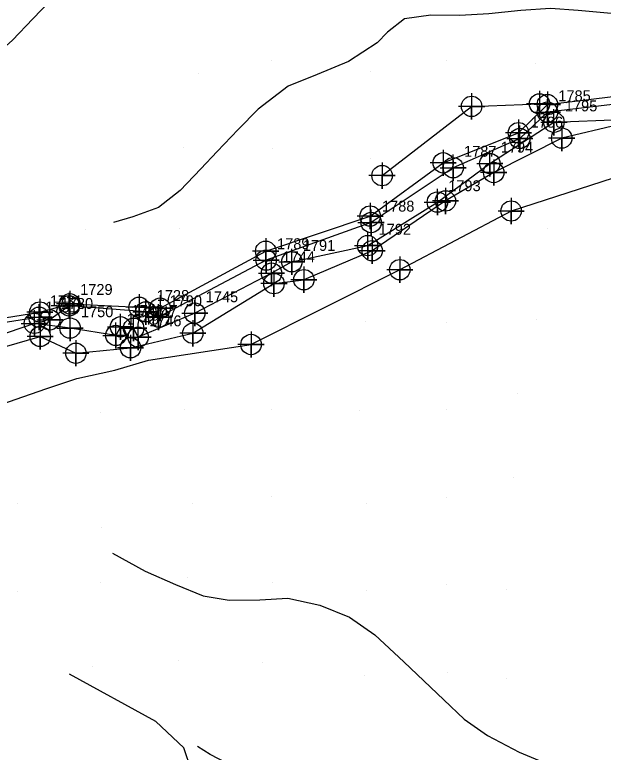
# Model space of a CAD drawing. Extents: x 1497074 to 1501343, y 481943 to 486114.
# Drawn here: x 1498608.9 to 1498743.8, y 484626.5 to 484795.7 of the extents above; entities that cross this region are included whole.
import ezdxf

# ---------------------------------------------------------------- set-up
doc = ezdxf.new("R2010")
doc.units = 0
for name, color, linetype in [('Exist DTM Breakline', 7, 'Continuous'), ('Exist DTM Breakline Cogo Point CELL', 7, 'Continuous'), ('Exist Hydro Stream or Body of Water', 7, 'Continuous'), ('Exist Hydro Stream or Body of Water Cogo Number', 7, 'Continuous'), ('Exist Hydro Stream or Body of Water Cogo Point CELL', 7, 'Continuous'), ('PH Exist DTM Breakline', 7, 'Continuous'), ('PH Exist DTM Point', 7, 'Continuous')]:
    doc.layers.add(name, color=color, linetype=linetype)

msp = doc.modelspace()

# ---------------------------------------------------------------- linework, layer by layer
at = {"layer": 'Exist DTM Breakline'}
for points in [[(1498642.2, 484728.41), (1498666.42, 484741.46), (1498690.37, 484749.54), (1498707.14, 484761.75), (1498724.39, 484768.67), (1498731.03, 484775.11), (1498755.48, 484778.15), (1498768.96, 484780.58), (1498783.61, 484785.4), (1498803.34, 484788.6), (1498815.05, 484790.23)], [(1498818.6, 484781.5), (1498803.72, 484775.91), (1498783.12, 484775.55), (1498771.11, 484773.41), (1498766.97, 484764.98), (1498756.64, 484762.17), (1498749.4, 484764.8), (1498747.24, 484770.45), (1498734.31, 484767.43), (1498718.71, 484759.53), (1498707.65, 484753), (1498690.86, 484741.59), (1498675.18, 484734.94)], [(1498693.11, 484758.81), (1498713.65, 484774.71), (1498729.23, 484775.27)], [(1498751.28, 484759.9), (1498722.71, 484750.7), (1498697.19, 484737.24), (1498663.06, 484720.07)], [(1498592.95, 484715.67), (1498614.71, 484721.92), (1498622.89, 484718.07), (1498635.42, 484719.32), (1498649.7, 484722.64), (1498668.32, 484734.04), (1498675.18, 484734.94)], [(1498561.97, 484712.06), (1498567.31, 484714.79), (1498573.02, 484716.73), (1498578.66, 484717.48), (1498586.51, 484720.09), (1498598.83, 484724.96), (1498614.61, 484727.53), (1498621.47, 484729.41), (1498637.39, 484728.61), (1498642.2, 484728.41)]]:
    msp.add_lwpolyline(points, dxfattribs=at)
at = {"layer": 'Exist DTM Breakline Cogo Point CELL'}
for points in [[(1498713.65, 484777.71), (1498713.65, 484771.71), (1498713.65, 484774.71), (1498716.65, 484774.71), (1498710.65, 484774.71)], [(1498729.23, 484778.27), (1498729.23, 484772.27), (1498729.23, 484775.27), (1498732.23, 484775.27), (1498726.23, 484775.27)], [(1498731.03, 484778.11), (1498731.03, 484772.11), (1498731.03, 484775.11), (1498734.03, 484775.11), (1498728.03, 484775.11)], [(1498724.39, 484771.67), (1498724.39, 484765.67), (1498724.39, 484768.67), (1498727.39, 484768.67), (1498721.39, 484768.67)], [(1498734.31, 484770.43), (1498734.31, 484764.43), (1498734.31, 484767.43), (1498737.31, 484767.43), (1498731.31, 484767.43)], [(1498707.14, 484764.75), (1498707.14, 484758.75), (1498707.14, 484761.75), (1498710.14, 484761.75), (1498704.14, 484761.75)], [(1498718.71, 484762.53), (1498718.71, 484756.53), (1498718.71, 484759.53), (1498721.71, 484759.53), (1498715.71, 484759.53)], [(1498693.11, 484761.81), (1498693.11, 484755.81), (1498693.11, 484758.81), (1498696.11, 484758.81), (1498690.11, 484758.81)], [(1498707.65, 484756), (1498707.65, 484750), (1498707.65, 484753), (1498710.65, 484753), (1498704.65, 484753)], [(1498690.37, 484752.54), (1498690.37, 484746.54), (1498690.37, 484749.54), (1498693.37, 484749.54), (1498687.37, 484749.54)], [(1498722.71, 484753.7), (1498722.71, 484747.7), (1498722.71, 484750.7), (1498725.71, 484750.7), (1498719.71, 484750.7)], [(1498666.42, 484744.46), (1498666.42, 484738.46), (1498666.42, 484741.46), (1498669.42, 484741.46), (1498663.42, 484741.46)], [(1498690.86, 484744.59), (1498690.86, 484738.59), (1498690.86, 484741.59), (1498693.86, 484741.59), (1498687.86, 484741.59)], [(1498697.19, 484740.24), (1498697.19, 484734.24), (1498697.19, 484737.24), (1498700.19, 484737.24), (1498694.19, 484737.24)], [(1498675.18, 484737.94), (1498675.18, 484731.94), (1498675.18, 484734.94), (1498678.18, 484734.94), (1498672.18, 484734.94)], [(1498668.32, 484737.04), (1498668.32, 484731.04), (1498668.32, 484734.04), (1498671.32, 484734.04), (1498665.32, 484734.04)], [(1498621.47, 484732.41), (1498621.47, 484726.41), (1498621.47, 484729.41), (1498624.47, 484729.41), (1498618.47, 484729.41)], [(1498614.61, 484730.53), (1498614.61, 484724.53), (1498614.61, 484727.53), (1498617.61, 484727.53), (1498611.61, 484727.53)], [(1498637.39, 484731.61), (1498637.39, 484725.61), (1498637.39, 484728.61), (1498640.39, 484728.61), (1498634.39, 484728.61)], [(1498642.2, 484731.41), (1498642.2, 484725.41), (1498642.2, 484728.41), (1498645.2, 484728.41), (1498639.2, 484728.41)], [(1498649.7, 484725.64), (1498649.7, 484719.64), (1498649.7, 484722.64), (1498652.7, 484722.64), (1498646.7, 484722.64)], [(1498614.71, 484724.92), (1498614.71, 484718.92), (1498614.71, 484721.92), (1498617.71, 484721.92), (1498611.71, 484721.92)], [(1498635.42, 484722.32), (1498635.42, 484716.32), (1498635.42, 484719.32), (1498638.42, 484719.32), (1498632.42, 484719.32)], [(1498663.06, 484723.07), (1498663.06, 484717.07), (1498663.06, 484720.07), (1498666.06, 484720.07), (1498660.06, 484720.07)], [(1498622.89, 484721.07), (1498622.89, 484715.07), (1498622.89, 484718.07), (1498625.89, 484718.07), (1498619.89, 484718.07)]]:
    msp.add_lwpolyline(points, dxfattribs=at)
for centre in [(1498713.65, 484774.71), (1498729.23, 484775.27), (1498731.03, 484775.11), (1498724.39, 484768.67), (1498734.31, 484767.43), (1498707.14, 484761.75), (1498693.11, 484758.81), (1498718.71, 484759.53), (1498707.65, 484753), (1498722.71, 484750.7), (1498690.37, 484749.54), (1498690.86, 484741.59), (1498666.42, 484741.46), (1498697.19, 484737.24), (1498675.18, 484734.94), (1498668.32, 484734.04), (1498621.47, 484729.41), (1498637.39, 484728.61), (1498642.2, 484728.41), (1498614.61, 484727.53), (1498614.71, 484721.92), (1498649.7, 484722.64), (1498663.06, 484720.07), (1498622.89, 484718.07), (1498635.42, 484719.32)]:
    msp.add_circle(centre, 2.34, dxfattribs=at)
at = {"layer": 'Exist Hydro Stream or Body of Water'}
for points in [[(1498815.48, 484787.21), (1498804.14, 484782.17), (1498784.36, 484782.64), (1498769.3, 484778.29), (1498757.64, 484776.52), (1498731.04, 484773.39), (1498724.7, 484767.33), (1498709.42, 484760.64), (1498690.59, 484748.07), (1498666.52, 484739.44), (1498641.87, 484726.36)], [(1498672.43, 484739.05), (1498689.81, 484742.76), (1498705.79, 484752.75), (1498717.83, 484761.59), (1498732.54, 484771.06), (1498747.88, 484771.66), (1498771.96, 484776.08), (1498782, 484777.24), (1498803.41, 484778.4), (1498816.84, 484784.96)], [(1498672.43, 484739.05), (1498667.77, 484736.45), (1498650.16, 484727.27), (1498637.17, 484721.75), (1498636.13, 484723.81), (1498633.12, 484724.13), (1498632.05, 484722.16), (1498621.54, 484723.84), (1498613.36, 484724.93), (1498592.05, 484717.66)], [(1498641.87, 484726.36), (1498638.93, 484727.56), (1498621.37, 484728.94), (1498616.9, 484725.74), (1498614.44, 484726.33), (1498598.42, 484723.81), (1498587.31, 484717.39), (1498578.44, 484715.65), (1498572.56, 484714.47), (1498568.25, 484712.81), (1498562.8, 484710.02)]]:
    msp.add_lwpolyline(points, dxfattribs=at)
at = {"layer": 'Exist Hydro Stream or Body of Water Cogo Point CELL'}
for points in [[(1498728.04, 484773.39), (1498734.04, 484773.39), (1498731.04, 484773.39), (1498731.04, 484770.39), (1498731.04, 484776.39)], [(1498729.54, 484771.06), (1498735.54, 484771.06), (1498732.54, 484771.06), (1498732.54, 484768.06), (1498732.54, 484774.06)], [(1498721.7, 484767.33), (1498727.7, 484767.33), (1498724.7, 484767.33), (1498724.7, 484764.33), (1498724.7, 484770.33)], [(1498714.83, 484761.59), (1498720.83, 484761.59), (1498717.83, 484761.59), (1498717.83, 484758.59), (1498717.83, 484764.59)], [(1498706.42, 484760.64), (1498712.42, 484760.64), (1498709.42, 484760.64), (1498709.42, 484757.64), (1498709.42, 484763.64)], [(1498702.79, 484752.75), (1498708.79, 484752.75), (1498705.79, 484752.75), (1498705.79, 484749.75), (1498705.79, 484755.75)], [(1498687.59, 484748.07), (1498693.59, 484748.07), (1498690.59, 484748.07), (1498690.59, 484745.07), (1498690.59, 484751.07)], [(1498686.81, 484742.76), (1498692.81, 484742.76), (1498689.81, 484742.76), (1498689.81, 484739.76), (1498689.81, 484745.76)], [(1498663.52, 484739.44), (1498669.52, 484739.44), (1498666.52, 484739.44), (1498666.52, 484736.44), (1498666.52, 484742.44)], [(1498669.43, 484739.05), (1498675.43, 484739.05), (1498672.43, 484739.05), (1498672.43, 484736.05), (1498672.43, 484742.05)], [(1498664.77, 484736.45), (1498670.77, 484736.45), (1498667.77, 484736.45), (1498667.77, 484733.45), (1498667.77, 484739.45)], [(1498618.37, 484728.94), (1498624.37, 484728.94), (1498621.37, 484728.94), (1498621.37, 484725.94), (1498621.37, 484731.94)], [(1498635.93, 484727.56), (1498641.93, 484727.56), (1498638.93, 484727.56), (1498638.93, 484724.56), (1498638.93, 484730.56)], [(1498611.44, 484726.33), (1498617.44, 484726.33), (1498614.44, 484726.33), (1498614.44, 484723.33), (1498614.44, 484729.33)], [(1498613.9, 484725.74), (1498619.9, 484725.74), (1498616.9, 484725.74), (1498616.9, 484722.74), (1498616.9, 484728.74)], [(1498638.87, 484726.36), (1498644.87, 484726.36), (1498641.87, 484726.36), (1498641.87, 484723.36), (1498641.87, 484729.36)], [(1498647.16, 484727.27), (1498653.16, 484727.27), (1498650.16, 484727.27), (1498650.16, 484724.27), (1498650.16, 484730.27)], [(1498610.36, 484724.93), (1498616.36, 484724.93), (1498613.36, 484724.93), (1498613.36, 484721.93), (1498613.36, 484727.93)], [(1498630.12, 484724.13), (1498636.12, 484724.13), (1498633.12, 484724.13), (1498633.12, 484721.13), (1498633.12, 484727.13)], [(1498618.54, 484723.84), (1498624.54, 484723.84), (1498621.54, 484723.84), (1498621.54, 484720.84), (1498621.54, 484726.84)], [(1498633.13, 484723.81), (1498639.13, 484723.81), (1498636.13, 484723.81), (1498636.13, 484720.81), (1498636.13, 484726.81)], [(1498629.05, 484722.16), (1498635.05, 484722.16), (1498632.05, 484722.16), (1498632.05, 484719.16), (1498632.05, 484725.16)], [(1498634.17, 484721.75), (1498640.17, 484721.75), (1498637.17, 484721.75), (1498637.17, 484718.75), (1498637.17, 484724.75)]]:
    msp.add_lwpolyline(points, dxfattribs=at)
for centre in [(1498731.04, 484773.39), (1498732.54, 484771.06), (1498724.7, 484767.33), (1498709.42, 484760.64), (1498717.83, 484761.59), (1498705.79, 484752.75), (1498690.59, 484748.07), (1498689.81, 484742.76), (1498666.52, 484739.44), (1498672.43, 484739.05), (1498667.77, 484736.45), (1498621.37, 484728.94), (1498614.44, 484726.33), (1498638.93, 484727.56), (1498641.87, 484726.36), (1498650.16, 484727.27), (1498613.36, 484724.93), (1498616.9, 484725.74), (1498621.54, 484723.84), (1498633.12, 484724.13), (1498636.13, 484723.81), (1498632.05, 484722.16), (1498637.17, 484721.75)]:
    msp.add_circle(centre, 2.34, dxfattribs=at)
at = {"layer": 'PH Exist DTM Breakline'}
for points in [[(1498543.58, 484748.88), (1498547.05, 484751.53), (1498562.17, 484766.44), (1498568.25, 484769.48), (1498573.77, 484771.58), (1498579.01, 484774.03), (1498583.19, 484777.03), (1498589.92, 484779.92), (1498596.37, 484782.13), (1498603.17, 484785.32), (1498608.38, 484789.9), (1498613.04, 484794.82), (1498618.97, 484801.06)], [(1498763.56, 484794.31), (1498744.83, 484796.11), (1498738.07, 484796.71), (1498731.78, 484797.17), (1498724.97, 484796.7), (1498717.62, 484795.94), (1498710.92, 484795.54), (1498704.32, 484795.61), (1498698.28, 484794.78), (1498694.33, 484791.72), (1498692.02, 484789.28), (1498685.41, 484785.03), (1498678.23, 484782.05), (1498671.57, 484779.37), (1498664.71, 484774.06), (1498660.11, 484769.43), (1498655.29, 484764.35), (1498651.54, 484760.4), (1498646.8, 484755.42), (1498641.81, 484751.48), (1498635.97, 484749.35), (1498631.53, 484748.05)], [(1498568.33, 484695.24), (1498574.65, 484695.27), (1498579.04, 484697.47), (1498585.37, 484699.59), (1498593.64, 484702.24), (1498601.55, 484704.87), (1498608.99, 484707.43), (1498616.19, 484709.99), (1498623.12, 484712.27), (1498631.79, 484714.21), (1498639.53, 484716.45), (1498663.06, 484720.07)], [(1498631.32, 484672.18), (1498638.78, 484668.07), (1498645.74, 484665.05), (1498652.08, 484662.44), (1498658.02, 484661.42), (1498665.09, 484661.49), (1498671.48, 484661.91), (1498678.83, 484660.27), (1498685.67, 484657.51), (1498691.48, 484653.45), (1498698.1, 484647.25), (1498704.19, 484641.46), (1498707.27, 484638.54), (1498711.94, 484634.11), (1498717.33, 484630.4), (1498724.54, 484626.58), (1498731.01, 484623.87), (1498736.56, 484621.51), (1498742.96, 484618.72), (1498747.59, 484616.58)], [(1498633.18, 484558.95), (1498648.11, 484582.16), (1498659.09, 484599.9), (1498663.4, 484606.06), (1498651.69, 484614.71), (1498649.44, 484622.31), (1498647.66, 484627.57), (1498641.26, 484633.6), (1498621.45, 484644.43)], [(1498727.2, 484584.84), (1498708.57, 484595.61), (1498701.95, 484600.97), (1498696.09, 484605.11), (1498689.09, 484609.83), (1498681.43, 484613.97), (1498675.21, 484616.82), (1498667.71, 484619.25), (1498661.7, 484621.92), (1498657.49, 484624.01), (1498653.72, 484626), (1498650.77, 484627.88)]]:
    msp.add_lwpolyline(points, dxfattribs=at)
at = {"layer": 'PH Exist DTM Point'}
for p, q in [((1498667.7, 484785.3), (1498667.7, 484785.3)), ((1498707.81, 484785.16), (1498707.81, 484785.16)), ((1498728.37, 484784.63), (1498728.37, 484784.63)), ((1498650.97, 484782.16), (1498650.97, 484782.16)), ((1498690.49, 484782.61), (1498690.49, 484782.61)), ((1498647.68, 484765.38), (1498647.68, 484765.38)), ((1498667.9, 484765.07), (1498667.9, 484765.07)), ((1498690.44, 484762.67), (1498690.44, 484762.67)), ((1498625.18, 484746.41), (1498625.18, 484746.41)), ((1498646.55, 484746.76), (1498646.55, 484746.76)), ((1498731.15, 484746.75), (1498731.15, 484746.75)), ((1498689.22, 484725.34), (1498689.22, 484725.34)), ((1498728.45, 484725.88), (1498728.45, 484725.88)), ((1498707.81, 484725.16), (1498707.81, 484725.16)), ((1498724.07, 484708.81), (1498724.07, 484708.81)), ((1498647.84, 484705.19), (1498647.84, 484705.19)), ((1498667.81, 484705.16), (1498667.81, 484705.16)), ((1498688.03, 484704.95), (1498688.03, 484704.95)), ((1498707.81, 484705.16), (1498707.81, 484705.16)), ((1498628.43, 484704.57), (1498628.43, 484704.57)), ((1498723.21, 484689.53), (1498723.21, 484689.53)), ((1498667.84, 484685.13), (1498667.84, 484685.13)), ((1498707.89, 484685.08), (1498707.89, 484685.08)), ((1498609.54, 484683.52), (1498609.54, 484683.52)), ((1498649.56, 484683.49), (1498649.56, 484683.49)), ((1498689.49, 484683.56), (1498689.49, 484683.56)), ((1498628.83, 484678.08), (1498628.83, 484678.08)), ((1498648.47, 484666.64), (1498648.47, 484666.64)), ((1498628.47, 484665.45), (1498628.47, 484665.45)), ((1498668.08, 484665.44), (1498668.08, 484665.44)), ((1498707.86, 484665.12), (1498707.86, 484665.12)), ((1498609.57, 484663.49), (1498609.57, 484663.49)), ((1498689.51, 484663.55), (1498689.51, 484663.55)), ((1498721.66, 484663.84), (1498721.66, 484663.84)), ((1498646.51, 484647.56), (1498646.51, 484647.56)), ((1498626.7, 484646.21), (1498626.7, 484646.21)), ((1498665.71, 484647.16), (1498665.71, 484647.16)), ((1498688.99, 484644.04), (1498688.99, 484644.04)), ((1498708.1, 484644.89), (1498708.1, 484644.89)), ((1498721.72, 484643.53), (1498721.72, 484643.53))]:
    msp.add_line(p, q, dxfattribs=at)

# ---------------------------------------------------------------- texts
at = {"layer": 'Exist Hydro Stream or Body of Water Cogo Number'}
for s, p in [('1785', (1498733.54, 484775.89)), ('1795', (1498735.04, 484773.56)), ('1786', (1498727.2, 484769.83)), ('1794', (1498720.33, 484764.09)), ('1787', (1498711.92, 484763.15)), ('1793', (1498708.29, 484755.25)), ('1788', (1498693.09, 484750.57)), ('1792', (1498692.31, 484745.26)), ('1789', (1498669.02, 484741.94)), ('1791', (1498674.93, 484741.55)), ('1744', (1498670.27, 484738.95)), ('1729', (1498623.87, 484731.45)), ('1728', (1498641.43, 484730.06)), ('1745', (1498652.66, 484729.77)), ('1731', (1498616.94, 484728.83)), ('1730', (1498619.4, 484728.24)), ('1790', (1498644.37, 484728.86)), ('1751', (1498615.86, 484727.43)), ('1750', (1498624.04, 484726.34)), ('1748', (1498635.62, 484726.63)), ('1747', (1498638.63, 484726.31)), ('1749', (1498634.55, 484724.66)), ('1746', (1498639.67, 484724.25))]:
    msp.add_text(s, height=2.5, dxfattribs=at).set_placement(p)

doc.saveas('drawing.dxf')
